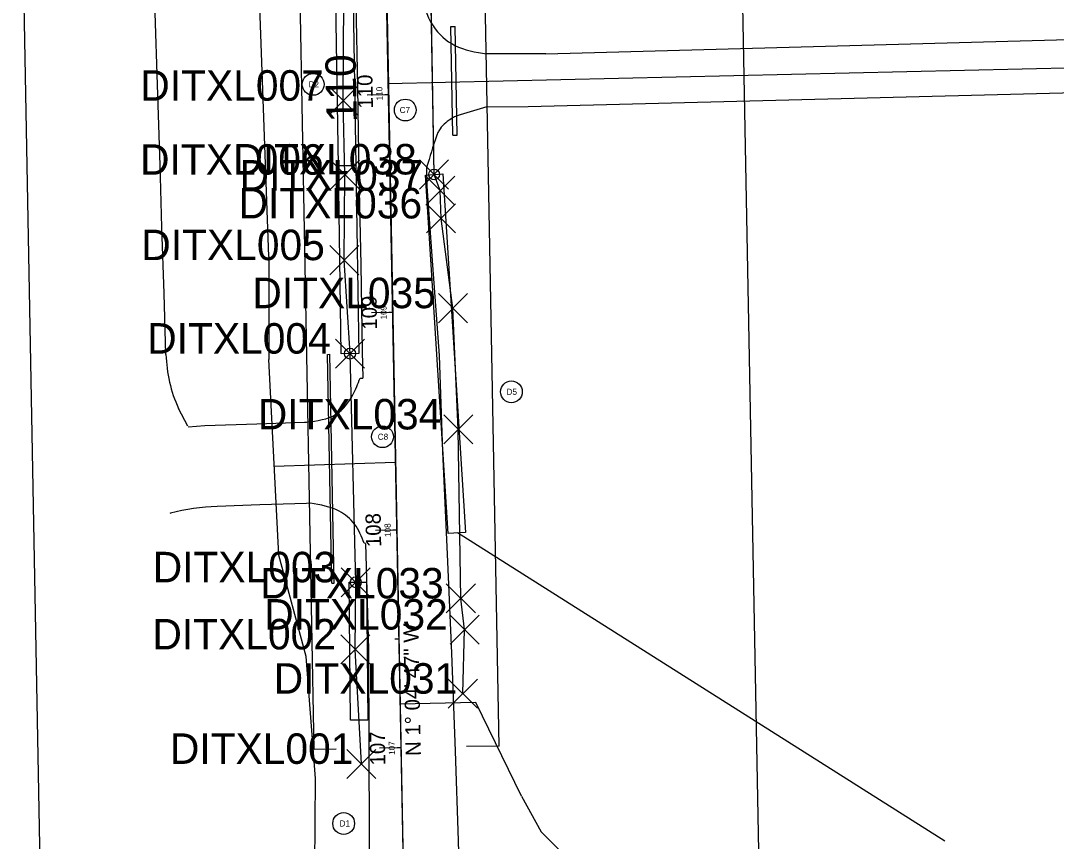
# Model space of a CAD drawing. Extents: x 2287043 to 2296348, y 637947 to 641293.
# Drawn here: x 2287213.5 to 2287689.3, y 638630.3 to 639007.3 of the extents above; entities that cross this region are included whole.
import ezdxf

# ---------------------------------------------------------------- set-up
doc = ezdxf.new("R2010")
doc.units = 0
for name, color, linetype in [('DR_P_Drainage_Area', 7, 'Continuous'), ('DR_P_Storm_Sewer', 7, 'Continuous'), ('GE_X_CL_100', 7, 'Continuous'), ('GE_X_CL_20', 7, 'Continuous'), ('GE_X_CL_50', 7, 'Continuous'), ('GK_Visualization', 7, 'Continuous'), ('RW_P_Prelim_RW', 7, 'Continuous'), ('SC_Scratch11', 7, 'Continuous'), ('SC_Scratch2', 7, 'Continuous'), ('SC_Scratch4', 7, 'Continuous'), ('SC_Scratch6', 7, 'Continuous'), ('SC_Scratch7', 7, 'Continuous'), ('SC_Scratch8', 7, 'Continuous'), ('SC_Scratch9', 7, 'Continuous')]:
    doc.layers.add(name, color=color, linetype=linetype)

msp = doc.modelspace()

# ---------------------------------------------------------------- linework, layer by layer
at = {"layer": 'DR_P_Drainage_Area'}
for p, q in [((2287327.5, 638898.94), (2287322.85, 639030.76)), ((2287382.2, 638978.38), (2287885.01, 638990.03)), ((2287385.58, 638804.32), (2287330, 638802.52))]:
    msp.add_line(p, q, dxfattribs=at)
for points in [[(2287365.99, 639861.68), (2287378.81, 639153.12), (2287391.95, 638476.45)], [(2287327.5, 638898.94), (2287327.5, 638851.7)], [(2287345.11, 638476.45), (2287340.17, 638532.29), (2287348.41, 638581.77), (2287348.51, 638598.52), (2287348.89, 638659.2), (2287344.64, 638715.18), (2287332.07, 638761.85), (2287327.5, 638851.7)], [(2287443.65, 638651.03), (2287422.55, 638694.04), (2287387.74, 638693.39)], [(2287443.65, 638651.03), (2287452.6, 638634.73), (2287487.26, 638600.34)]]:
    msp.add_lwpolyline(points, dxfattribs=at)
at = {"layer": 'DR_P_Storm_Sewer'}
for p, q in [((2287411.17, 639004.64), (2287413.17, 639004.68)), ((2287412.11, 638954.65), (2287411.17, 639004.64)), ((2287414.11, 638954.69), (2287413.17, 639004.68)), ((2287412.11, 638954.65), (2287414.11, 638954.69)), ((2287354.54, 638854.02), (2287355.54, 638854.04)), ((2287356.52, 638748.94), (2287354.54, 638854.02)), ((2287357.52, 638748.96), (2287355.54, 638854.04)), ((2287356.52, 638748.94), (2287357.52, 638748.96))]:
    msp.add_line(p, q, dxfattribs=at)
at = {"layer": 'GE_X_CL_100'}
for p, q in [((2287401.6, 637973.38), (2287357.08, 640335.42)), ((2287382.76, 638973.2), (2287372.76, 638973.02)), ((2287384.64, 638873.22), (2287374.64, 638873.03)), ((2287386.53, 638773.24), (2287376.53, 638773.05)), ((2287388.41, 638673.26), (2287378.41, 638673.07))]:
    msp.add_line(p, q, dxfattribs=at)
at = {"layer": 'GE_X_CL_20'}
for p, q in [((2287401.6, 637973.38), (2287357.08, 640335.42)), ((2287382.76, 638973.2), (2287380.76, 638973.17)), ((2287383.7, 638923.21), (2287381.7, 638923.18)), ((2287384.64, 638873.22), (2287382.64, 638873.18)), ((2287385.58, 638823.23), (2287383.58, 638823.19)), ((2287386.53, 638773.24), (2287384.53, 638773.2)), ((2287387.47, 638723.25), (2287385.47, 638723.21)), ((2287388.41, 638673.26), (2287386.41, 638673.22))]:
    msp.add_line(p, q, dxfattribs=at)
at = {"layer": 'GE_X_CL_50'}
for p, q in [((2287401.6, 637973.38), (2287357.08, 640335.42)), ((2287382.76, 638973.2), (2287377.76, 638973.11)), ((2287382.76, 638973.2), (2287377.76, 638973.11)), ((2287384.64, 638873.22), (2287379.64, 638873.13)), ((2287384.64, 638873.22), (2287379.64, 638873.13)), ((2287386.53, 638773.24), (2287381.53, 638773.15)), ((2287386.53, 638773.24), (2287381.53, 638773.15)), ((2287388.41, 638673.26), (2287383.41, 638673.16)), ((2287388.41, 638673.26), (2287383.41, 638673.16))]:
    msp.add_line(p, q, dxfattribs=at)
at = {"layer": 'GK_Visualization'}
for p, q in [((2287403.46, 638936.65), (2287401.96, 639022.65)), ((2287361.74, 638970.54), (2287361.96, 639016.55)), ((2287355.08, 638963.87), (2287368.41, 638977.22)), ((2287355.08, 638977.22), (2287368.41, 638963.87)), ((2287362.51, 638936.53), (2287361.74, 638970.54)), ((2287355.84, 638929.85), (2287369.18, 638943.2)), ((2287355.84, 638943.2), (2287369.18, 638929.85)), ((2287396.8, 638929.97), (2287410.13, 638943.32)), ((2287396.8, 638943.32), (2287410.13, 638929.97)), ((2287362.2, 638897.29), (2287362.51, 638936.53)), ((2287399.6, 638922.57), (2287412.93, 638935.92)), ((2287399.6, 638935.92), (2287412.93, 638922.57)), ((2287406.26, 638929.25), (2287403.46, 638936.65)), ((2287406.67, 638916.45), (2287406.26, 638929.25)), ((2287400.01, 638909.78), (2287413.34, 638923.13)), ((2287400.01, 638923.13), (2287413.34, 638909.78)), ((2287412.1, 638875.23), (2287406.67, 638916.45)), ((2287355.53, 638890.61), (2287368.86, 638903.96)), ((2287355.53, 638903.96), (2287368.86, 638890.61)), ((2287364.81, 638854.36), (2287362.2, 638897.29)), ((2287405.44, 638868.56), (2287418.77, 638881.91)), ((2287405.44, 638881.91), (2287418.77, 638868.56)), ((2287414.51, 638819.53), (2287412.1, 638875.23)), ((2287358.15, 638847.68), (2287371.48, 638861.03)), ((2287358.15, 638861.03), (2287371.48, 638847.68)), ((2287367.44, 638749.32), (2287364.81, 638854.36)), ((2287407.85, 638812.86), (2287421.18, 638826.21)), ((2287407.85, 638826.21), (2287421.18, 638812.86)), ((2287415.72, 638741.9), (2287414.51, 638819.53)), ((2287360.78, 638742.64), (2287374.11, 638755.99)), ((2287360.78, 638755.99), (2287374.11, 638742.64)), ((2287367.2, 638718.49), (2287367.44, 638749.32)), ((2287409.05, 638735.23), (2287422.39, 638748.58)), ((2287409.05, 638748.58), (2287422.39, 638735.23)), ((2287417.46, 638727.59), (2287415.72, 638741.9)), ((2287410.8, 638720.92), (2287424.13, 638734.27)), ((2287410.8, 638734.27), (2287424.13, 638720.92)), ((2287360.53, 638711.81), (2287373.86, 638725.16)), ((2287360.53, 638725.16), (2287373.86, 638711.81)), ((2287416.65, 638698.16), (2287417.46, 638727.59)), ((2287370.07, 638665.9), (2287367.2, 638718.49)), ((2287409.98, 638691.49), (2287423.31, 638704.84)), ((2287409.98, 638704.84), (2287423.31, 638691.49)), ((2287363.4, 638659.22), (2287376.73, 638672.57)), ((2287363.4, 638672.57), (2287376.73, 638659.22))]:
    msp.add_line(p, q, dxfattribs=at)
at = {"layer": 'RW_P_Prelim_RW'}
for p, q in [((2287348.42, 638672.5), (2287326.8, 639819.59)), ((2287433.4, 638674.11), (2287411.84, 639818.25)), ((2287358.42, 638672.69), (2287348.42, 638672.5)), ((2287433.4, 638674.11), (2287418.4, 638673.82))]:
    msp.add_line(p, q, dxfattribs=at)
at = {"layer": 'SC_Scratch11'}
for points in [[(2287360.81, 638854.26), (2287359.46, 638940.67), (2287367.46, 638940.79), (2287368.81, 638854.39)], [(2287409.9, 638771.72), (2287399.47, 638936.39), (2287407.46, 638936.9), (2287417.88, 638772.23)], [(2287364.98, 638685.94), (2287364.42, 638749.31), (2287372.42, 638749.38), (2287372.98, 638686.01)]]:
    msp.add_lwpolyline(points, close=True, dxfattribs=at)
at = {"layer": 'SC_Scratch2'}
msp.add_lwpolyline([(2287223.14, 638587.24), (2287213.53, 639097.15), (2287543.47, 639103.37), (2287553.08, 638593.46)], close=True, dxfattribs=at)
at = {"layer": 'SC_Scratch4'}
for p, q in [((2287400.03, 638939.91), (2287400.07, 638931.07)), ((2287369.43, 638843.11), (2287370.66, 638843.13)), ((2287290.29, 638820.98), (2287285.99, 638829.19)), ((2287344.89, 638822.92), (2287344.89, 638822.92)), ((2287282.3, 638781.09), (2287282.02, 638780.87)), ((2287371.95, 638767.2), (2287371.3, 638767.25))]:
    msp.add_line(p, q, dxfattribs=at)
for points in [[(2287364.94, 639161.35), (2287365.38, 639140.22), (2287366.04, 639097.42), (2287366.85, 639056.45), (2287367.51, 639015.53), (2287368.23, 638976.63), (2287368.94, 638936.33), (2287369.74, 638895.15), (2287370.39, 638855.41), (2287370.66, 638843.13)], [(2287277.68, 638935.54), (2287277.57, 638940.74), (2287276.27, 638982.52), (2287273.98, 639053.49), (2287273.58, 639073.5)], [(2287454.77, 638992.01), (2287840.18, 639002.66), (2287892.69, 639000.88), (2287940.85, 638988.96), (2287985.38, 638962.58), (2288042.66, 638928.64)], [(2287454.77, 638992.01), (2287441.47, 638992.02), (2287427.56, 638992.01)], [(2287446.71, 638967.88), (2287835.97, 638977.79), (2287888.31, 638974.69), (2287917.42, 638970.98), (2287968.4, 638941.99), (2288009.47, 638918.63), (2288034.31, 638904.5)], [(2287427.62, 638967.7), (2287446.71, 638967.88)], [(2287280.27, 638853.99), (2287279.42, 638881.98), (2287278.42, 638912.36), (2287277.68, 638935.54)], [(2287400.07, 638931.07), (2287402.74, 638895.05), (2287405.71, 638853.45), (2287407.36, 638809.27), (2287409.49, 638762.27), (2287411.49, 638716.81), (2287413.14, 638671.69), (2287414.43, 638630.77), (2287415.74, 638586.02), (2287416.9, 638545.29), (2287417.53, 638523.81)], [(2287290.45, 638820.68), (2287298.17, 638821.27), (2287322.03, 638822.15), (2287343.89, 638822.89), (2287344.89, 638822.92)], [(2287346.67, 638785.61), (2287344.87, 638785.54), (2287323.31, 638784.87), (2287303.81, 638784.06)], [(2287371.95, 638767.2), (2287373.28, 638718.62), (2287373.47, 638673.87), (2287373.54, 638632.64), (2287374, 638587.11), (2287374.45, 638546.92), (2287375.16, 638522.93)]]:
    msp.add_lwpolyline(points, dxfattribs=at)
for centre, radius, start, end in [((2287345.31, 638855.92), 65.07, 181.6987, 204.2527), ((2287306.8, 638683.03), 101.08, 91.6965, 104.0278)]:
    msp.add_arc(centre, radius, start, end, dxfattribs=at)
for points in [[(2287397.08, 639021.08), (2287402.95, 639004.87), (2287413, 638995.92), (2287427.56, 638992.01)], [(2287427.62, 638967.7), (2287415.44, 638964.09), (2287414.56, 638963.8), (2287413.68, 638963.46), (2287411.95, 638962.62), (2287408.76, 638960.39), (2287406.17, 638957.54), (2287405.21, 638955.93), (2287404.82, 638955.09), (2287404.51, 638954.22), (2287400.03, 638939.91)], [(2287344.89, 638822.92), (2287358.36, 638826.49), (2287366.11, 638835.39), (2287369.43, 638843.11)], [(2287371.3, 638767.25), (2287366.88, 638776.04), (2287359.87, 638782.01), (2287346.67, 638785.61)]]:
    msp.add_spline(points, degree=3, dxfattribs=at)
at = {"layer": 'SC_Scratch6'}
msp.add_line((2287638.09, 638630.35), (2287414.21, 638771.97), dxfattribs=at)
at = {"layer": 'SC_Scratch7'}
for points in [[(2287370.07, 638665.9), (2287367.2, 638718.49), (2287367.44, 638749.32), (2287364.81, 638854.36), (2287362.2, 638897.29), (2287362.51, 638936.53), (2287361.74, 638970.54), (2287361.96, 639016.55), (2287358.87, 639055.82), (2287357.77, 639098.75), (2287359.14, 639129.78), (2287360.05, 639157.19), (2287360, 639160.7), (2287358.79, 639217.68), (2287357.05, 639239.4), (2287356.58, 639282.73), (2287354.63, 639331.64), (2287353.72, 639354.51), (2287354.17, 639372.48), (2287352.98, 639418.42), (2287351.79, 639473.08)], [(2287416.65, 638698.16), (2287417.46, 638727.59), (2287415.72, 638741.9), (2287414.51, 638819.53), (2287412.1, 638875.23), (2287406.67, 638916.45), (2287406.26, 638929.25), (2287403.46, 638936.65), (2287401.96, 639022.65), (2287399.93, 639112.47), (2287397.68, 639197.97), (2287396.32, 639261.68), (2287395.31, 639334.71)]]:
    msp.add_lwpolyline(points, dxfattribs=at)
for centre in [(2287403.46, 638936.65), (2287364.81, 638854.36), (2287367.44, 638749.32)]:
    msp.add_circle(centre, 2.5, dxfattribs=at)
at = {"layer": 'SC_Scratch8'}
for centre in [(2287347.89, 638978.04), (2287390.21, 638966.26), (2287438.96, 638836.82), (2287379.73, 638816.18), (2287361.9, 638638.53)]:
    msp.add_circle(centre, 5, dxfattribs=at)
at = {"layer": 'SC_Scratch9'}
msp.add_lwpolyline([(2287359.46, 638940.67), (2287358.28, 639015.66), (2287366.28, 639015.78), (2287367.46, 638940.79)], close=True, dxfattribs=at)

# ---------------------------------------------------------------- texts
at = {"layer": 'GE_X_CL_100'}
msp.add_text('110', height=14, rotation=91.0798, dxfattribs=at).set_placement((2287367.99, 638960.75))
at = {"layer": 'GE_X_CL_20'}
for s, p in [('110', (2287379.8, 638970.71)), ('109', (2287381.7, 638870.1)), ('108', (2287383.58, 638770.16)), ('107', (2287385.47, 638670.06))]:
    msp.add_text(s, height=2.8, rotation=91.0798, dxfattribs=at).set_placement(p)
at = {"layer": 'GE_X_CL_50'}
for s, p in [('110', (2287375.37, 638966.98)), ('110', (2287375.37, 638966.98)), ('109', (2287377.29, 638865.42)), ('109', (2287377.29, 638865.42)), ('108', (2287379.17, 638765.55)), ('108', (2287379.17, 638765.55)), ('N 1%%d 04\' 47" W', (2287397.39, 638669.61)), ('107', (2287381.06, 638665.27)), ('107', (2287381.06, 638665.27))]:
    msp.add_text(s, height=7, rotation=91.0798, dxfattribs=at).set_placement(p)
at = {"layer": 'GK_Visualization'}
for s, p in [('DITXL007', (2287268.49, 638970.54)), ('DITXL006', (2287268.38, 638936.53)), ('DITXL038', (2287311.2, 638936.65)), ('DITXL037', (2287314.11, 638929.25)), ('DITXL036', (2287313.64, 638916.45)), ('DITXL005', (2287268.95, 638897.29)), ('DITXL035', (2287319.96, 638875.23)), ('DITXL004', (2287271.67, 638854.36)), ('DITXL034', (2287322.47, 638819.53)), ('DITXL003', (2287274.19, 638749.32)), ('DITXL033', (2287323.57, 638741.9)), ('DITXL032', (2287325.43, 638727.59)), ('DITXL002', (2287274.05, 638718.49)), ('DITXL031', (2287329.76, 638698.16)), ('DITXL001', (2287282.08, 638665.9))]:
    msp.add_text(s, height=14, dxfattribs=at).set_placement(p)
at = {"layer": 'SC_Scratch8'}
for s, p in [('D2', (2287345.76, 638976.64)), ('C7', (2287387.63, 638964.86)), ('D5', (2287436.74, 638835.42)), ('C8', (2287377.56, 638814.78)), ('D1', (2287360.03, 638637.13))]:
    msp.add_text(s, height=2.8, dxfattribs=at).set_placement(p)

doc.saveas('drawing.dxf')
